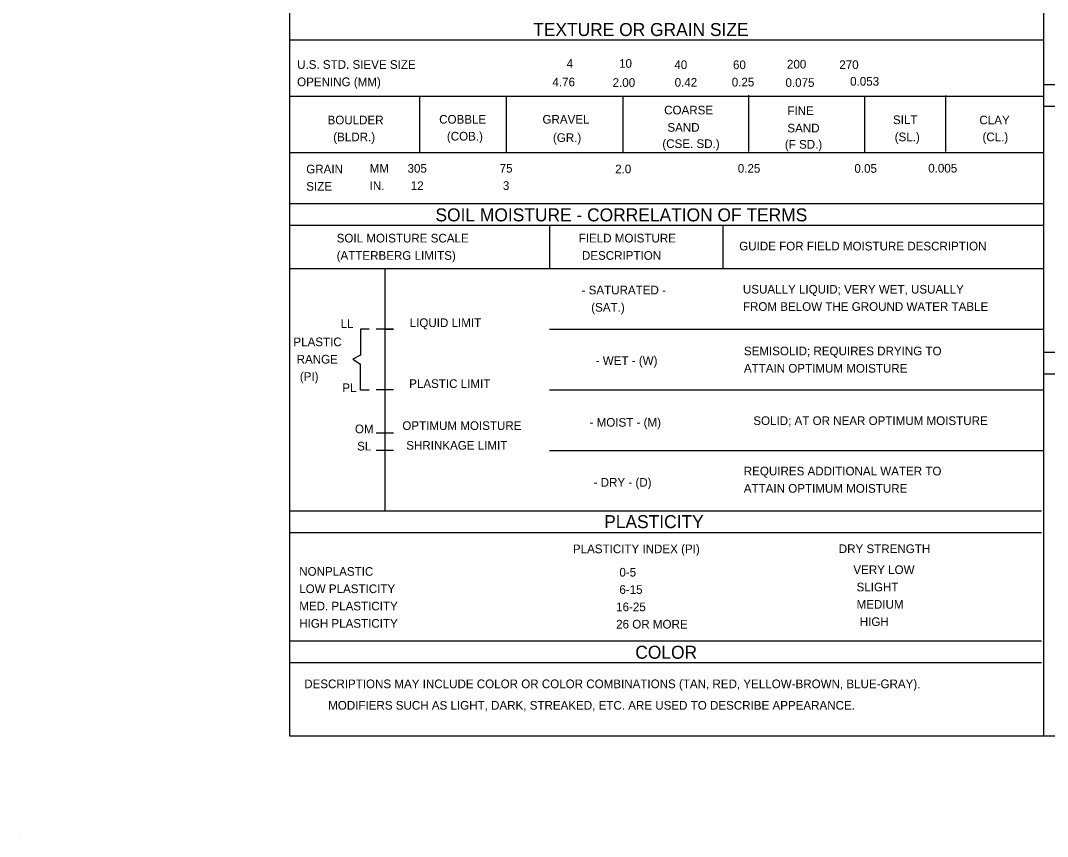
# Model space of a CAD drawing. Extents: x 278710 to 279187, y 171464 to 171625.
# Drawn here: x 278991.9 to 279043.3, y 171480.8 to 171521.6 of the extents above; entities that cross this region are included whole.
import ezdxf

# ---------------------------------------------------------------- set-up
doc = ezdxf.new("R2010")
doc.units = 0
doc.layers.add('Prop Strc Sect_ Misc - User Comment (Tx - small)', color=7, linetype='Continuous')

msp = doc.modelspace()

# ---------------------------------------------------------------- linework, layer by layer
at = {"layer": 'Prop Strc Sect_ Misc - User Comment (Tx - small)'}
for p, q in [((279005.33, 171581.203), (279005.33, 171485.806)), ((279043.07, 171566.02), (279043.07, 171485.806)), ((279005.33, 171520.671), (279043.07, 171520.671)), ((279043.07, 171518.437), (279081.678, 171518.437)), ((279005.33, 171517.851), (279043.07, 171517.851)), ((279011.837, 171517.851), (279011.837, 171515.031)), ((279016.175, 171517.851), (279016.175, 171515.031)), ((279022.022, 171517.851), (279022.022, 171515.031)), ((279028.299, 171517.894), (279028.299, 171515.075)), ((279034.108, 171517.851), (279034.108, 171515.031)), ((279038.173, 171517.89), (279038.173, 171515.07)), ((279043.07, 171517.352), (279081.678, 171517.352)), ((279005.33, 171515.031), (279043.07, 171515.031)), ((279005.33, 171512.468), (279043.07, 171512.468)), ((279005.33, 171511.383), (279043.07, 171511.383)), ((279018.344, 171511.383), (279018.344, 171509.214)), ((279027.02, 171511.383), (279027.02, 171509.214)), ((279005.33, 171509.214), (279043.07, 171509.214)), ((279010.101, 171509.214), (279010.101, 171497.068)), ((279010.535, 171506.178), (279009.668, 171506.178)), ((279010.101, 171506.178), (279010.535, 171506.178)), ((279018.344, 171506.178), (279043.07, 171506.178)), ((279121.332, 171505.006), (279043.07, 171505.006)), ((279121.332, 171503.922), (279043.07, 171503.922)), ((279010.535, 171503.141), (279009.668, 171503.141)), ((279018.344, 171503.141), (279043.07, 171503.141)), ((279010.535, 171500.972), (279009.668, 171500.972)), ((279010.535, 171500.104), (279009.668, 171500.104)), ((279018.344, 171500.104), (279043.07, 171500.104)), ((279005.33, 171497.068), (279042.97, 171497.068)), ((279005.33, 171495.983), (279042.97, 171495.983)), ((279005.33, 171490.561), (279042.97, 171490.561)), ((279005.33, 171489.476), (279042.97, 171489.476)), ((279005.33, 171485.806), (279158.027, 171485.806)), ((278991.866, 171480.763), (278991.866, 171480.763))]:
    msp.add_line(p, q, dxfattribs=at)
for points in [[(279009.316, 171506.173), (279008.882, 171506.173), (279008.882, 171504.872)], [(279008.882, 171504.872), (279008.492, 171504.668), (279008.882, 171504.425)], [(279009.316, 171503.124), (279008.882, 171503.124), (279008.882, 171504.425)]]:
    msp.add_lwpolyline(points, dxfattribs=at)

# ---------------------------------------------------------------- texts
for s, height, p in [('TEXTURE OR GRAIN SIZE', 0.6507, (279017.528, 171520.862)), ('U.S. STD. SIEVE SIZE', 0.43381, (279005.711, 171519.218)), ('4    ', 0.4338, (279019.203, 171519.27)), ('10', 0.4338, (279021.827, 171519.27)), (' 40 ', 0.4338, (279024.434, 171519.209)), (' 60   ', 0.4338, (279027.367, 171519.205)), (' 200', 0.4338, (279030.069, 171519.235)), ('   270', 0.4338, (279032.368, 171519.209)), ('OPENING (MM)', 0.43381, (279005.711, 171518.35)), ('4.76   ', 0.4338, (279018.491, 171518.341)), ('2.00', 0.4338, (279021.502, 171518.315)), ('0.42', 0.4338, (279024.608, 171518.324)), ('0.25', 0.4338, (279027.466, 171518.337)), ('0.075', 0.4338, (279030.156, 171518.315)), ('0.053', 0.4338, (279033.392, 171518.376)), ('COARSE', 0.4338, (279024.083, 171516.936)), ('FINE', 0.4338, (279030.251, 171516.901)), ('BOULDER', 0.4338, (279007.234, 171516.437)), ('COBBLE', 0.4338, (279012.821, 171516.472)), ('GRAVEL', 0.4338, (279017.992, 171516.472)), (' SAND', 0.4338, (279024.083, 171516.068)), ('SAND', 0.4338, (279030.251, 171516.033)), ('SILT', 0.4338, (279035.539, 171516.45)), ('CLAY', 0.4338, (279039.864, 171516.437)), ('(BLDR.)', 0.4338, (279007.52, 171515.591)), ('(COB.)', 0.4338, (279013.207, 171515.626)), ('(GR.)', 0.4338, (279018.517, 171515.556)), ('(SL.)', 0.4338, (279035.622, 171515.591)), ('(CL.)', 0.4338, (279040.016, 171515.591)), ('(CSE. SD.)', 0.4338, (279023.992, 171515.253)), ('(F SD.)', 0.4338, (279030.126, 171515.218)), ('GRAIN', 0.4338, (279006.167, 171513.982)), ('MM', 0.4338, (279009.342, 171514.016)), ('305', 0.4338, (279011.238, 171514.016)), ('75', 0.4338, (279015.849, 171514.02)), ('2.0', 0.4338, (279021.632, 171513.986)), ('0.25', 0.4338, (279027.77, 171514.016)), ('0.05', 0.4338, (279033.605, 171514.012)), ('0.005', 0.4338, (279037.301, 171514.025)), ('SIZE', 0.4338, (279006.167, 171513.114)), ('IN.', 0.4338, (279009.342, 171513.149)), (' 12', 0.4338, (279011.238, 171513.149)), (' 3', 0.4338, (279015.849, 171513.153)), ('SOIL MOISTURE - CORRELATION OF TERMS', 0.6507, (279012.635, 171511.578)), ('SOIL MOISTURE SCALE', 0.43381, (279007.69, 171510.52)), ('FIELD MOISTURE', 0.43381, (279019.806, 171510.52)), ('GUIDE FOR FIELD MOISTURE DESCRIPTION', 0.43381, (279027.84, 171510.121)), ('(ATTERBERG LIMITS)', 0.43381, (279007.69, 171509.652)), (' DESCRIPTION', 0.43381, (279019.806, 171509.652)), ('- SATURATED -', 0.43381, (279019.949, 171507.921)), ('USUALLY LIQUID; VERY WET, USUALLY', 0.43381, (279028.026, 171507.96)), ('   (SAT.)', 0.4338, (279019.949, 171507.054)), ('FROM BELOW THE GROUND WATER TABLE', 0.43381, (279028.026, 171507.093)), ('LIQUID LIMIT', 0.43381, (279011.346, 171506.282)), ('LL', 0.4338, (279007.889, 171506.243)), ('PLASTIC', 0.4338, (279005.525, 171505.323)), ('SEMISOLID; REQUIRES DRYING TO', 0.43381, (279028.074, 171504.867)), (' RANGE', 0.4338, (279005.525, 171504.455)), ('- WET - (W)', 0.43381, (279020.656, 171504.386)), ('ATTAIN OPTIMUM MOISTURE', 0.43381, (279028.074, 171504)), ('  (PI)', 0.4338, (279005.525, 171503.588)), ('PLASTIC LIMIT', 0.43381, (279011.32, 171503.232)), ('PL', 0.4338, (279007.976, 171503.024)), ('OPTIMUM MOISTURE', 0.43381, (279010.978, 171501.128)), ('- MOIST - (M)', 0.43381, (279020.348, 171501.293)), ('SOLID; AT OR NEAR OPTIMUM MOISTURE', 0.43381, (279028.547, 171501.375)), ('OM', 0.4338, (279008.605, 171500.963)), ('SL', 0.4338, (279008.713, 171500.1)), ('SHRINKAGE LIMIT', 0.43381, (279011.173, 171500.139)), ('REQUIRES ADDITIONAL WATER TO', 0.43381, (279028.069, 171498.851)), ('- DRY - (D)', 0.43381, (279020.552, 171498.287)), ('ATTAIN OPTIMUM MOISTURE', 0.43381, (279028.069, 171497.983)), ('PLASTICITY', 0.6507, (279021.081, 171496.209)), ('PLASTICITY INDEX (PI)', 0.43381, (279019.515, 171494.955)), ('DRY STRENGTH', 0.43381, (279032.824, 171494.959)), ('NONPLASTIC', 0.4338, (279005.816, 171493.823)), (' 0-5', 0.4338, (279021.68, 171493.784)), ('VERY LOW', 0.4338, (279033.553, 171493.91)), ('LOW PLASTICITY', 0.43381, (279005.816, 171492.955)), (' 6-15', 0.4338, (279021.68, 171492.916)), (' SLIGHT', 0.4338, (279033.553, 171493.042)), ('MED. PLASTICITY', 0.43381, (279005.816, 171492.088)), ('16-25', 0.4338, (279021.68, 171492.049)), (' MEDIUM', 0.4338, (279033.553, 171492.174)), ('HIGH PLASTICITY', 0.43381, (279005.816, 171491.22)), ('26 OR MORE', 0.4338, (279021.68, 171491.181)), ('  HIGH', 0.4338, (279033.553, 171491.307)), ('COLOR', 0.6507, (279022.638, 171489.667)), ('DESCRIPTIONS MAY INCLUDE COLOR OR COLOR COMBINATIONS (TAN, RED, YELLOW-BROWN, BLUE-GRAY).', 0.43381, (279006.066, 171488.192)), ('MODIFIERS SUCH AS LIGHT, DARK, STREAKED, ETC. ARE USED TO DESCRIBE APPEARANCE.', 0.43381, (279007.264, 171487.116))]:
    msp.add_text(s, height=height, dxfattribs=at).set_placement(p)

doc.saveas('drawing.dxf')
